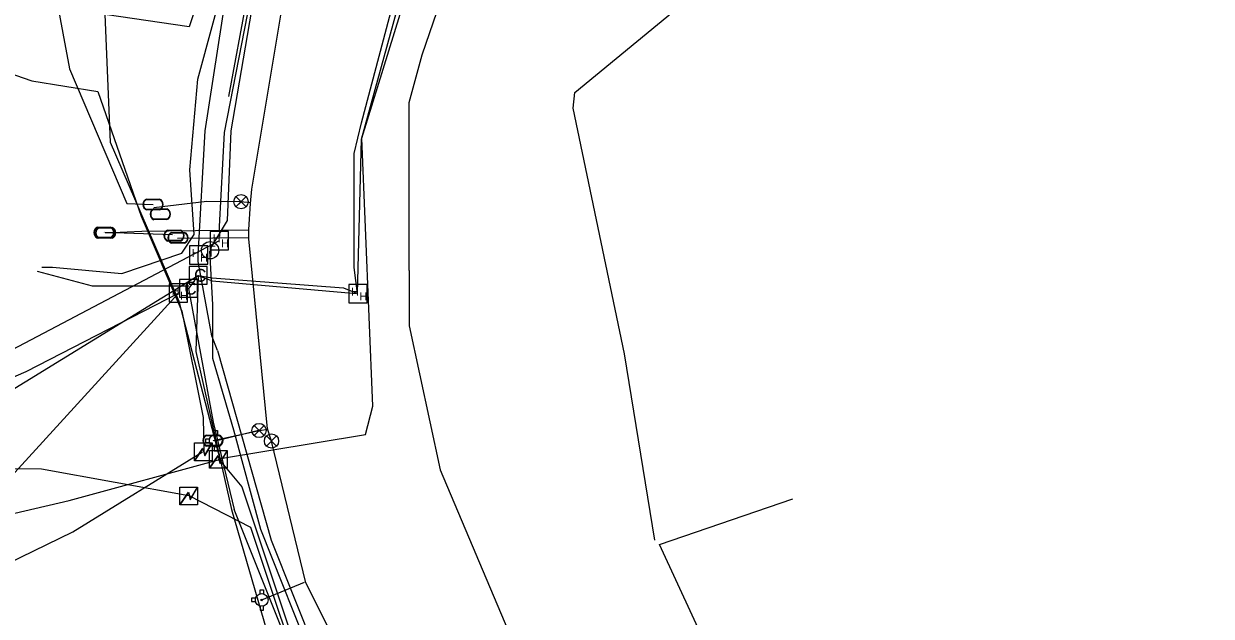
# Model space of a CAD drawing. Extents: x 2070721 to 2083039, y 729290 to 737883.
# Drawn here: x 2080173.8 to 2080544.7, y 734130.6 to 734315.9 of the extents above; entities that cross this region are included whole.
import ezdxf

# ---------------------------------------------------------------- set-up
doc = ezdxf.new("R2010")
doc.units = 0
for name, color, linetype in [('Cogo Default Point CELL', 7, 'Continuous'), ('COGO Default Point Elevation', 7, 'Continuous'), ('COGO Default Point Number', 7, 'Continuous'), ('Exist Utilities Power Pole CELL', 7, 'Continuous'), ('Exist Utilities Power Pole Cogo Elevation', 7, 'Continuous'), ('Exist Utilities Telephone UG Cable Cogo Point CELL', 7, 'Continuous'), ('Exist Utilities Telephone UG Cable SUE LOS C Cogo Comment', 7, 'Continuous'), ('Exist Utilities Telephone UG Cable SUE LOS C Cogo Number', 7, 'Continuous'), ('Exist Utilities Telephone UG Cable SUE LOS C Cogo Point CELL', 7, 'Continuous'), ('Exist Utilities Telephone UG FO Cogo Point CELL', 7, 'Continuous'), ('Exist Utilities Telephone UG FO SUE LOS B Cogo Number', 7, 'Continuous'), ('Exist Utilities TV Pedestal CELL', 7, 'Continuous'), ('Exist Utilities TV Pedestal Cogo Elevation', 7, 'Continuous'), ('Exist Utilities TV UG Cable Cogo Point CELL', 7, 'Continuous'), ('Exist Utilities TV UG Cable SUE LOS C Cogo Comment', 7, 'Continuous'), ('Exist Utilities TV UG Cable SUE LOS C Cogo Elevation', 7, 'Continuous'), ('Exist Utilities TV UG Cable SUE LOS C Cogo Number', 7, 'Continuous'), ('Exist Utilities TV UG Cable SUE LOS C Cogo Point CELL', 7, 'Continuous'), ('Exist Utilities Water UG Line SUE LOS B Cogo Elevation', 7, 'Continuous'), ('Exist Utilities Water UG Line SUE LOS B Cogo Number', 7, 'Continuous')]:
    doc.layers.add(name, color=color, linetype=linetype)

msp = doc.modelspace()

# ---------------------------------------------------------------- linework, layer by layer
at = {"layer": 'Cogo Default Point CELL'}
for p, q in [((2080228.33, 734237.2), (2080228.33, 734237.2)), ((2080225.3, 734233.17), (2080225.3, 734233.17))]:
    msp.add_line(p, q, dxfattribs=at)
for points in [[(2080225.55, 734234.43), (2080231.1, 734234.43), (2080231.1, 734239.97), (2080225.55, 734239.97), (2080225.55, 734234.43)], [(2080222.52, 734230.39), (2080228.07, 734230.39), (2080228.07, 734235.94), (2080222.52, 734235.94), (2080222.52, 734230.39)]]:
    msp.add_lwpolyline(points, dxfattribs=at)
at = {"layer": 'COGO Default Point Elevation'}
for points in [[(2080243.28, 734261.8), (2080240.12, 734258.65), (2080241.7, 734260.22), (2080243.28, 734258.65), (2080240.12, 734261.8)], [(2080248.92, 734190.28), (2080245.77, 734187.12), (2080247.34, 734188.7), (2080248.92, 734187.12), (2080245.77, 734190.28)], [(2080252.8, 734186.99), (2080249.66, 734183.84), (2080251.23, 734185.42), (2080252.8, 734183.84), (2080249.66, 734186.99)]]:
    msp.add_lwpolyline(points, dxfattribs=at)
for centre in [(2080241.7, 734260.22), (2080247.34, 734188.7), (2080251.23, 734185.42)]:
    msp.add_circle(centre, 2.23, dxfattribs=at)
at = {"layer": 'COGO Default Point Number'}
for p, q in [((2080233.8, 734185.5), (2080233.8, 734185.5)), ((2080248.17, 734135.75), (2080248.17, 734135.75))]:
    msp.add_line(p, q, dxfattribs=at)
for points in [[(2080233.29, 734187.41), (2080233.29, 734188.7), (2080234.31, 734188.7), (2080234.31, 734187.39)], [(2080231.89, 734186.01), (2080230.6, 734186.01), (2080230.6, 734184.99), (2080231.89, 734184.99)], [(2080233.29, 734183.59), (2080233.29, 734182.3), (2080234.31, 734182.3), (2080234.31, 734183.61)], [(2080247.66, 734137.66), (2080247.66, 734138.95), (2080248.68, 734138.95), (2080248.68, 734137.64)], [(2080246.26, 734136.26), (2080244.97, 734136.26), (2080244.97, 734135.24), (2080246.26, 734135.24)], [(2080247.66, 734133.84), (2080247.66, 734132.55), (2080248.68, 734132.55), (2080248.68, 734133.86)]]:
    msp.add_lwpolyline(points, dxfattribs=at)
for centre, radius in [((2080233.8, 734185.5), 1.98), ((2080233.8, 734185.5), 0.243), ((2080248.17, 734135.75), 1.98), ((2080248.17, 734135.75), 0.243)]:
    msp.add_circle(centre, radius, dxfattribs=at)
at = {"layer": 'Exist Utilities Power Pole CELL'}
msp.add_lwpolyline([(2080232.24, 734245.67), (2080237.5, 734254.36), (2080238.66, 734282.35), (2080245.75, 734323.83), (2080258.86, 734369.55), (2080269.86, 734398.57), (2080309.08, 734449.32), (2080323.63, 734464.88), (2080355.41, 734492.16), (2080379.52, 734509.8), (2080416.03, 734529.49), (2080502.71, 734562.3), (2080573.96, 734587.12), (2080616.57, 734603.22), (2080677.16, 734624.99), (2080749, 734651.22), (2080815.57, 734674.3), (2080861.11, 734690.56), (2080923.26, 734714.15), (2080934.26, 734720.97)], dxfattribs=at)
at = {"layer": 'Exist Utilities Power Pole Cogo Elevation'}
msp.add_lwpolyline([(2080225.45, 734168.4), (2080244.65, 734158.51), (2080253.95, 734130.69), (2080282.75, 734048.52), (2080295.34, 734028.75), (2080340.63, 733997.06), (2080355.06, 733989.84), (2080368.99, 733977.25), (2080380.73, 733968.31), (2080393.86, 733970.13), (2080428.86, 733995.36), (2080444.29, 734010.08)], dxfattribs=at)
at = {"layer": 'Exist Utilities Telephone UG Cable Cogo Point CELL'}
msp.add_line((2080278.21, 734231.5), (2080278.21, 734231.5), dxfattribs=at)
msp.add_lwpolyline([(2080275.34, 734228.63), (2080281.09, 734228.63), (2080281.09, 734234.38), (2080275.34, 734234.38), (2080275.34, 734228.63)], dxfattribs=at)
at = {"layer": 'Exist Utilities Telephone UG Cable SUE LOS C Cogo Comment'}
msp.add_lwpolyline([(2080237.92, 734293.08), (2080243.61, 734324.09), (2080258.34, 734369.36), (2080269.39, 734398.77), (2080286.02, 734425.45), (2080301.91, 734450.14), (2080317.89, 734467.75), (2080331.23, 734480.5), (2080381.43, 734521.31), (2080414.27, 734537.75), (2080416.02, 734538.24)], dxfattribs=at)
at = {"layer": 'Exist Utilities Telephone UG Cable SUE LOS C Cogo Number'}
for p, q in [((2080230.02, 734182.19), (2080230.02, 734182.19)), ((2080234.72, 734179.83), (2080234.72, 734179.83)), ((2080225.45, 734168.4), (2080225.45, 734168.4))]:
    msp.add_line(p, q, dxfattribs=at)
for points in [[(2080227.17, 734184.81), (2080232.73, 734184.81), (2080232.73, 734179.25), (2080227.17, 734179.25)], [(2080231.88, 734182.44), (2080237.43, 734182.44), (2080237.43, 734176.89), (2080231.88, 734176.89)], [(2080222.61, 734171.01), (2080228.16, 734171.01), (2080228.16, 734165.46), (2080222.61, 734165.46)]]:
    msp.add_lwpolyline(points, close=True, dxfattribs=at)
for points in [[(2080227.17, 734179.25), (2080229.82, 734183.2), (2080230.45, 734180.99), (2080232.73, 734184.81)], [(2080227.24, 734179.25), (2080229.82, 734182.99), (2080230.4, 734180.81), (2080232.73, 734184.65)], [(2080231.88, 734176.89), (2080234.52, 734180.84), (2080235.15, 734178.63), (2080237.43, 734182.44)], [(2080231.95, 734176.89), (2080234.52, 734180.63), (2080235.11, 734178.44), (2080237.43, 734182.29)], [(2080222.61, 734165.46), (2080225.25, 734169.4), (2080225.88, 734167.19), (2080228.16, 734171.01)], [(2080222.68, 734165.46), (2080225.25, 734169.19), (2080225.84, 734167.01), (2080228.16, 734170.86)]]:
    msp.add_lwpolyline(points, dxfattribs=at)
at = {"layer": 'Exist Utilities Telephone UG Cable SUE LOS C Cogo Point CELL'}
msp.add_circle((2080232.05, 734245.04), 2.72, dxfattribs=at)
at = {"layer": 'Exist Utilities Telephone UG FO Cogo Point CELL'}
for p, q in [((2080214.25, 734259.36), (2080214.25, 734259.36)), ((2080216.51, 734256.31), (2080216.51, 734256.31)), ((2080198.9, 734250.57), (2080198.9, 734250.57)), ((2080199.4, 734250.49), (2080199.4, 734250.49)), ((2080220.81, 734249.62), (2080220.81, 734249.62)), ((2080222.04, 734248.94), (2080222.04, 734248.94)), ((2080232.95, 734185.55), (2080232.95, 734185.55))]:
    msp.add_line(p, q, dxfattribs=at)
for points in [[(2080212.21, 734261.06), (2080216.29, 734261.06)], [(2080212.21, 734260.92), (2080216.29, 734260.92)], [(2080216.29, 734257.8), (2080212.19, 734257.8)], [(2080216.29, 734257.66), (2080212.19, 734257.66)], [(2080214.47, 734258.01), (2080218.55, 734258.01)], [(2080214.47, 734257.87), (2080218.55, 734257.87)], [(2080196.86, 734252.27), (2080200.94, 734252.27)], [(2080196.86, 734252.13), (2080200.94, 734252.13)], [(2080197.36, 734252.19), (2080201.44, 734252.19)], [(2080197.36, 734252.05), (2080201.44, 734252.05)], [(2080218.55, 734254.75), (2080214.45, 734254.75)], [(2080218.55, 734254.61), (2080214.45, 734254.61)], [(2080200.94, 734249.01), (2080196.84, 734249.01)], [(2080200.94, 734248.87), (2080196.84, 734248.87)], [(2080201.44, 734248.93), (2080197.34, 734248.93)], [(2080201.44, 734248.79), (2080197.34, 734248.79)], [(2080222.84, 734248.06), (2080218.74, 734248.06)], [(2080222.84, 734247.92), (2080218.74, 734247.92)], [(2080218.77, 734251.32), (2080222.84, 734251.32)], [(2080218.77, 734251.18), (2080222.84, 734251.18)], [(2080220, 734250.64), (2080224.08, 734250.64)], [(2080220, 734250.5), (2080224.08, 734250.5)], [(2080224.08, 734247.38), (2080219.98, 734247.38)], [(2080224.08, 734247.24), (2080219.98, 734247.24)], [(2080230.91, 734187.25), (2080234.99, 734187.25)], [(2080230.91, 734187.11), (2080234.99, 734187.11)], [(2080234.99, 734183.99), (2080230.89, 734183.99)], [(2080234.99, 734183.85), (2080230.89, 734183.85)]]:
    msp.add_lwpolyline(points, dxfattribs=at)
for centre, radius, start, end in [((2080212.94, 734259.35), 1.86, 113.178, 245.9794), ((2080212.95, 734259.35), 1.73, 115.3009, 243.7824), ((2080215.54, 734259.36), 1.86, 293.6483, 66.3084), ((2080215.55, 734259.36), 1.73, 295.1272, 64.8728), ((2080215.2, 734256.3), 1.86, 113.178, 245.9794), ((2080215.22, 734256.3), 1.73, 115.3009, 243.7824), ((2080217.8, 734256.31), 1.86, 293.6483, 66.3084), ((2080217.82, 734256.31), 1.73, 295.1272, 64.8728), ((2080197.59, 734250.56), 1.86, 113.178, 245.9794), ((2080197.6, 734250.56), 1.73, 115.3009, 243.7824), ((2080198.09, 734250.48), 1.86, 113.178, 245.9794), ((2080198.1, 734250.48), 1.73, 115.3009, 243.7824), ((2080200.19, 734250.57), 1.86, 293.6483, 66.3084), ((2080200.2, 734250.57), 1.73, 295.1272, 64.8728), ((2080200.69, 734250.49), 1.86, 293.6483, 66.3084), ((2080200.7, 734250.49), 1.73, 295.1272, 64.8728), ((2080219.5, 734249.61), 1.86, 113.178, 245.9794), ((2080219.51, 734249.61), 1.73, 115.3009, 243.7824), ((2080220.73, 734248.93), 1.86, 113.178, 245.9794), ((2080220.74, 734248.93), 1.73, 115.3009, 243.7824), ((2080222.1, 734249.62), 1.86, 293.6483, 66.3084), ((2080222.11, 734249.62), 1.73, 295.1272, 64.8728), ((2080223.33, 734248.94), 1.86, 293.6483, 66.3084), ((2080223.34, 734248.94), 1.73, 295.1272, 64.8728), ((2080231.64, 734185.54), 1.86, 113.178, 245.9794), ((2080231.65, 734185.54), 1.73, 115.3009, 243.7824), ((2080234.24, 734185.55), 1.86, 293.6483, 66.3084), ((2080234.25, 734185.55), 1.73, 295.1272, 64.8728)]:
    msp.add_arc(centre, radius, start, end, dxfattribs=at)
at = {"layer": 'Exist Utilities Telephone UG FO SUE LOS B Cogo Number'}
for p, q in [((2080232.12, 734250.92), (2080232.12, 734245.2)), ((2080237.84, 734250.92), (2080232.12, 734250.92)), ((2080234.98, 734248.06), (2080234.98, 734248.06)), ((2080237.84, 734245.2), (2080237.84, 734250.92)), ((2080225.59, 734246.39), (2080225.59, 734240.67)), ((2080231.31, 734246.39), (2080225.59, 734246.39)), ((2080231.31, 734240.67), (2080231.31, 734246.39)), ((2080232.12, 734245.2), (2080237.84, 734245.2)), ((2080225.59, 734240.67), (2080231.31, 734240.67)), ((2080228.45, 734243.53), (2080228.45, 734243.53)), ((2080219.31, 734234.5), (2080219.31, 734228.77)), ((2080225.03, 734234.5), (2080219.31, 734234.5)), ((2080225.03, 734228.77), (2080225.03, 734234.5)), ((2080222.17, 734231.63), (2080222.17, 734231.63)), ((2080219.31, 734228.77), (2080225.03, 734228.77))]:
    msp.add_line(p, q, dxfattribs=at)
at = {"layer": 'Exist Utilities TV Pedestal CELL'}
for points in [[(2080232.67, 734236.44), (2080273.72, 734233.3), (2080278.08, 734231.48), (2080279.38, 734279.77), (2080300.6, 734357.07), (2080319.92, 734390.91), (2080356.3, 734435.5), (2080369.79, 734448.44), (2080390.27, 734462.8), (2080376.9, 734455.01)], [(2080227.31, 734235.69), (2080225.31, 734233.11), (2080233, 734191.29), (2080239.52, 734164.02)], [(2080321.01, 734022.31), (2080305.36, 734043.56), (2080269.25, 734089.82), (2080239.52, 734164.02)]]:
    msp.add_lwpolyline(points, dxfattribs=at)
at = {"layer": 'Exist Utilities TV Pedestal Cogo Elevation'}
for p, q in [((2080199.2, 734250.67), (2080220.33, 734250)), ((2080221.83, 734248.87), (2080243.91, 734249.03)), ((2080233.76, 734185.47), (2080247.2, 734188.81)), ((2080248.24, 734135.8), (2080261.53, 734141.3))]:
    msp.add_line(p, q, dxfattribs=at)
for points in [[(2080357.06, 734003.27), (2080353.32, 734006.79), (2080296.63, 734072.2), (2080261.95, 734141.13), (2080251.22, 734185.42), (2080250, 734189.2), (2080244.12, 734248.6), (2080244.13, 734251.5), (2080244.63, 734259.68), (2080245.13, 734264.1), (2080254.44, 734320.44), (2080276.53, 734380.91), (2080391.41, 734503.18), (2080497.9, 734548.7), (2080500.72, 734549.83), (2080585.45, 734578.7), (2080702.53, 734619.89), (2080710.17, 734622.62), (2080743.51, 734634.52), (2080754.26, 734638.28), (2080902.52, 734692.58), (2081024.44, 734735.33)], [(2080176.61, 734363.96), (2080186.04, 734312.89), (2080188.09, 734301.77)], [(2080188.09, 734301.77), (2080206.09, 734259.71), (2080214.28, 734259.37)], [(2080214.47, 734258.36), (2080231.01, 734260.34), (2080241.56, 734260.28), (2080244.72, 734260)], [(2080244.2, 734251.31), (2080210.77, 734250.86), (2080199.35, 734250.43)], [(2080232.98, 734185.57), (2080247.35, 734188.69), (2080250.15, 734189.17)]]:
    msp.add_lwpolyline(points, dxfattribs=at)
at = {"layer": 'Exist Utilities TV UG Cable Cogo Point CELL'}
for points in [[(2080179.48, 734239.75), (2080182.79, 734239.75), (2080204.44, 734237.74), (2080223.27, 734244.14), (2080227.06, 734249.97), (2080225.75, 734270.22), (2080228.23, 734298.53), (2080237.75, 734333.83), (2080246.14, 734355.32), (2080258.39, 734393.6), (2080274.22, 734418.19), (2080320.87, 734477.75), (2080344.36, 734497.56), (2080358.62, 734490.18), (2080387.98, 734454.99)], [(2080294.22, 734238.68), (2080294.22, 734255.9), (2080294.22, 734291.26), (2080298.27, 734306.08), (2080307.66, 734333.57), (2080322.1, 734363.11), (2080329.68, 734375.34), (2080358.78, 734411), (2080382.14, 734437.37), (2080392.23, 734444.72), (2080389.38, 734455.18)], [(2080291.1, 734070.12), (2080273.08, 734096.26), (2080264.86, 734115.07), (2080247.85, 734157.71), (2080239.41, 734188.85), (2080232.9, 734211.26), (2080232.9, 734228.12), (2080231.97, 734244.9)], [(2080294.22, 734238.68), (2080294.22, 734221.46), (2080303.86, 734176.45), (2080326.14, 734123.68), (2080343.11, 734086.02), (2080369.71, 734062.6), (2080410.57, 734039.8), (2080423.78, 734028.65), (2080421.38, 734022.96), (2080402.46, 733993.71), (2080385.13, 733965.19), (2080355.27, 733912.59), (2080339.2, 733870.84), (2080335.53, 733861.67)]]:
    msp.add_lwpolyline(points, dxfattribs=at)
at = {"layer": 'Exist Utilities TV UG Cable SUE LOS C Cogo Comment'}
for points in [[(2080234.71, 734179.89), (2080280.62, 734187.44), (2080282.92, 734196.34), (2080279.43, 734280.03), (2080304.76, 734362.13), (2080356.55, 734435.67), (2080374.96, 734451.44)], [(2080370.98, 734154.39), (2080361.51, 734212.64), (2080345.43, 734289.41), (2080345.93, 734294.31), (2080384.7, 734326.31), (2080421.96, 734373.11), (2080453.41, 734409.54), (2080468.5, 734430.99)], [(2080242.66, 734403.28), (2080241.67, 734362.84), (2080225.56, 734314.83), (2080199.19, 734318.7), (2080200.86, 734278.87), (2080222.27, 734229.12), (2080235.32, 734178.97)], [(2080111.69, 734308.48), (2080119.26, 734311.71), (2080135.22, 734307.67), (2080154.56, 734303.8), (2080166.01, 734301.54), (2080176.37, 734298.05), (2080196.98, 734294.69), (2080210.47, 734255.68), (2080223.19, 734226.04), (2080229.85, 734192.73), (2080230.05, 734182.23)], [(2079937.52, 734192.32), (2079957.19, 734181.58), (2080020.32, 734166.12), (2080064.52, 734156.78), (2080106.22, 734147.77), (2080188.06, 734166.87), (2080235.43, 734179.74)], [(2080225.42, 734168.33), (2080179.4, 734176.66), (2080141.16, 734176.91), (2080123.55, 734183.66)], [(2080133.41, 734166.28), (2080133.92, 734165.53), (2080152.74, 734139.3), (2080189.19, 734157.01), (2080229.69, 734182.03)], [(2080234.72, 734179.83), (2080241.98, 734171.12), (2080276.22, 734068.16), (2080293.76, 734026.09), (2080325.21, 734006.15), (2080360.35, 733978.15), (2080376.41, 733964.84), (2080394.21, 733967.31), (2080427.72, 733990.11), (2080441.72, 734003.26), (2080444.29, 734010.08)], [(2080443.09, 734017.91), (2080429.26, 734056.79), (2080388.33, 734118.62), (2080372.45, 734153.12), (2080414.03, 734167.36)]]:
    msp.add_lwpolyline(points, dxfattribs=at)
at = {"layer": 'Exist Utilities TV UG Cable SUE LOS C Cogo Elevation'}
msp.add_lwpolyline([(2080228.33, 734237.2), (2080227.59, 734213.41), (2080238.77, 734164.01), (2080249.82, 734126.01), (2080269.26, 734089.95), (2080305.09, 734043.13), (2080320.73, 734021.92)], dxfattribs=at)
at = {"layer": 'Exist Utilities TV UG Cable SUE LOS C Cogo Number'}
for points in [[(2080278.08, 734231.48), (2080277, 734239.67), (2080277, 734275.25), (2080279.3, 734284.9), (2080288.08, 734317.87), (2080293.24, 734335.92), (2080296.25, 734346.26), (2080298.88, 734355.59), (2080304.96, 734366.83), (2080310.77, 734377.58), (2080320.31, 734392.98), (2080332.74, 734409.06), (2080345.11, 734424.32), (2080353.93, 734435.35), (2080365.15, 734446.1), (2080376.65, 734455.86), (2080394.1, 734462.75), (2080415.44, 734468.86), (2080444.8, 734480.86), (2080490.14, 734502.72), (2080540.63, 734520.42), (2080564.59, 734528.02)], [(2080228.33, 734237.2), (2080232.7, 734235.49), (2080277.64, 734231.55)]]:
    msp.add_lwpolyline(points, dxfattribs=at)
at = {"layer": 'Exist Utilities TV UG Cable SUE LOS C Cogo Point CELL'}
for points in [[(2080235.11, 734249.36), (2080234.94, 734252.48), (2080236.58, 734281.87), (2080244.62, 734323.58), (2080257.8, 734369.84), (2080268.59, 734399.28), (2080285.42, 734425.78), (2080306.49, 734446.52), (2080318.99, 734464.89), (2080332.07, 734479.26), (2080365.28, 734504.24), (2080415, 734536.31), (2080432.75, 734546.34), (2080471.85, 734557.5), (2080502.31, 734568.65), (2080534.18, 734580.2), (2080570.94, 734591.77), (2080576.66, 734593.81), (2080717.24, 734648.01)], [(2080228.28, 734243.43), (2080230.55, 734282.39), (2080237.1, 734324.84), (2080265.61, 734400.42), (2080300.19, 734451.55), (2080329.83, 734482.91), (2080380.99, 734522.11), (2080413.6, 734539.64), (2080433.63, 734544.47), (2080470.56, 734559.5), (2080533.58, 734581.77), (2080652.68, 734625.4)], [(2079959.83, 734188.33), (2080105.23, 734179.43), (2080123.21, 734189.25), (2080234.98, 734248.06)], [(2080234.38, 734213.72), (2080232.6, 734218.25), (2080228.35, 734241.54), (2080228.28, 734243.43)], [(2080234.38, 734213.72), (2080232.6, 734218.25), (2080228.35, 734241.54), (2080228.28, 734243.43)], [(2080222.28, 734231.61), (2080174.53, 734207.04), (2080146.45, 734195)], [(2080234.38, 734213.72), (2080251.15, 734154.39), (2080272, 734101.95), (2080285.47, 734081.3)]]:
    msp.add_lwpolyline(points, dxfattribs=at)
at = {"layer": 'Exist Utilities Water UG Line SUE LOS B Cogo Elevation'}
msp.add_lwpolyline([(2079959.93, 734183.76), (2080108.68, 734169.55), (2080152.84, 734190.77), (2080228.33, 734237.2), (2080232.67, 734236.44)], dxfattribs=at)
at = {"layer": 'Exist Utilities Water UG Line SUE LOS B Cogo Number'}
msp.add_line((2080147.53, 734149.79), (2080222.17, 734231.63), dxfattribs=at)
msp.add_lwpolyline([(2080225.43, 734233.87), (2080195.29, 734233.87), (2080178.12, 734238.44)], dxfattribs=at)

# ---------------------------------------------------------------- texts
at = {"layer": 'Cogo Default Point CELL'}
for p in [(2080227.02, 734235.2), (2080223.99, 734231.17)]:
    msp.add_text('C', height=4, dxfattribs=at).set_placement(p)
at = {"layer": 'Exist Utilities Telephone UG Cable Cogo Point CELL'}
for p in [(2080276.12, 734230.86), (2080278.7, 734229.4)]:
    msp.add_text('H', height=2.5, dxfattribs=at).set_placement(p)
at = {"layer": 'Exist Utilities Telephone UG Cable SUE LOS C Cogo Point CELL'}
msp.add_text('T', height=3.5, dxfattribs=at).set_placement((2080230.88, 734243.03))
at = {"layer": 'Exist Utilities Telephone UG FO SUE LOS B Cogo Number'}
for p in [(2080232.9, 734247.47), (2080235.47, 734246), (2080226.37, 734242.94), (2080228.94, 734241.47), (2080220.09, 734231.04), (2080222.66, 734229.58)]:
    msp.add_text('H', height=2.5, dxfattribs=at).set_placement(p)

doc.saveas('drawing.dxf')
